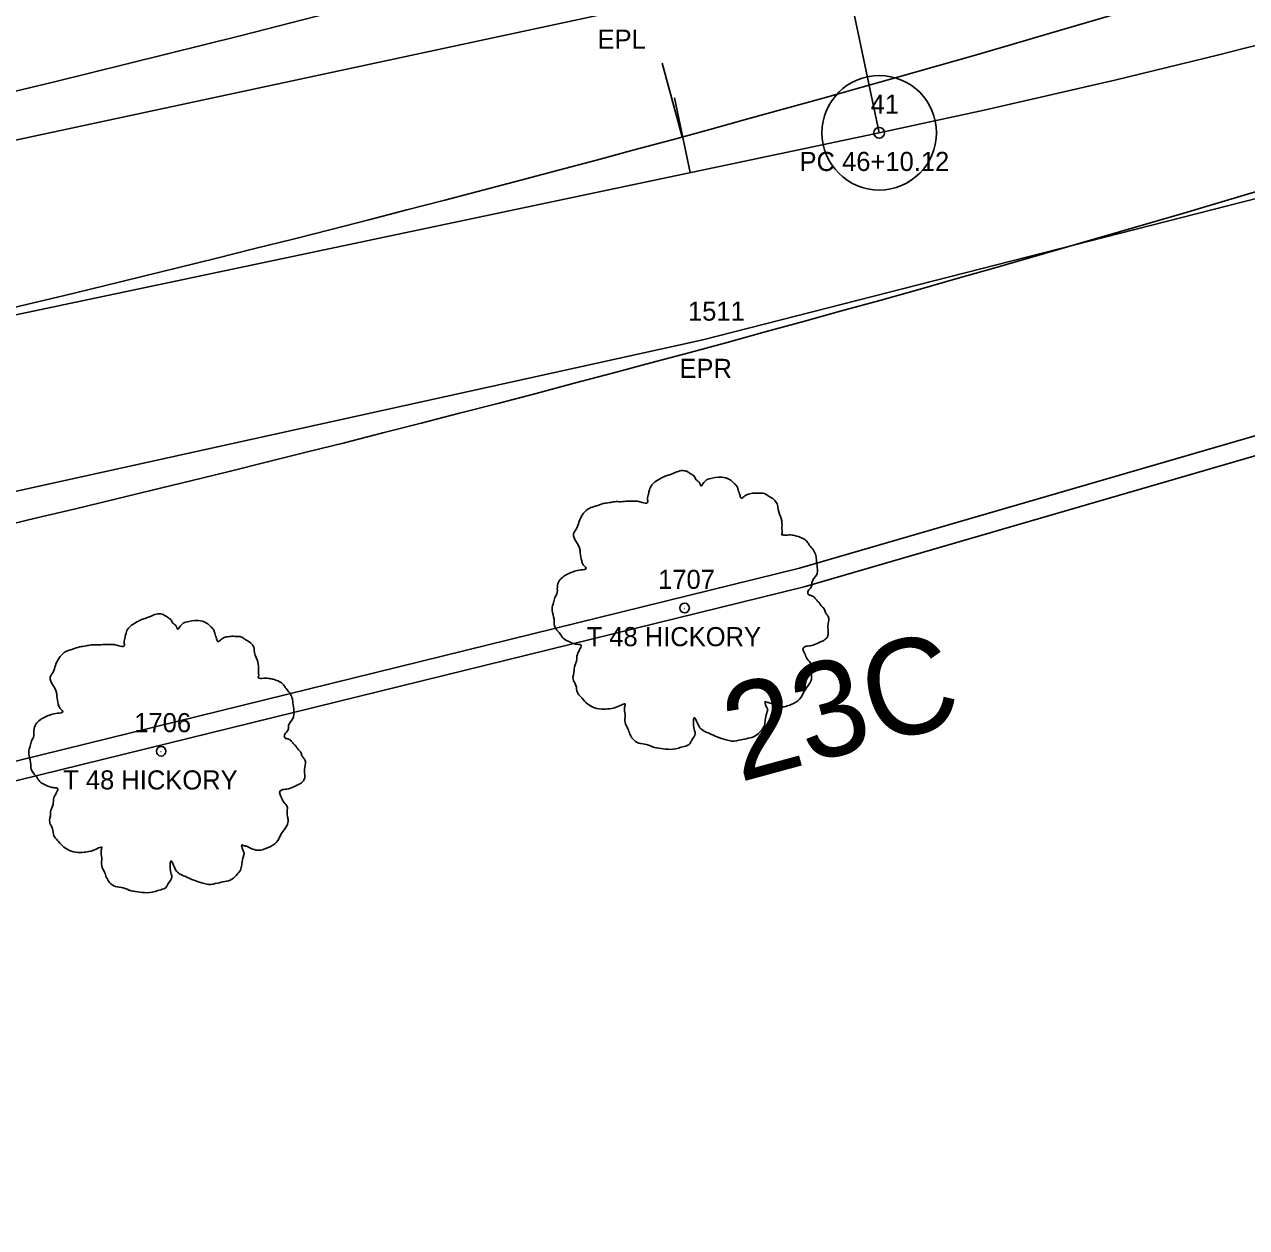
# Model space of a CAD drawing. Extents: x 1964982 to 1970452, y 1116335 to 1119906.
# Drawn here: x 1966640.1 to 1966704.1, y 1117364.6 to 1117427.6 of the extents above; entities that cross this region are included whole.
import ezdxf

# ---------------------------------------------------------------- set-up
doc = ezdxf.new("R2010")
doc.units = 0
for name, color, linetype in [('RD_EX_DV_Prop', 7, 'Continuous'), ('RD_EX_Road', 7, 'Continuous'), ('RD_EX_Road_txCode', 7, 'Continuous'), ('RD_EX_RW', 7, 'Continuous'), ('RD_EX_VEG', 7, 'Continuous'), ('RD_EX_VEG_txCode', 7, 'Continuous'), ('RD_HC_CL', 7, 'Continuous'), ('RD_HC_CL_Rel', 7, 'Continuous'), ('RD_HC_Data', 7, 'Continuous'), ('RD_HC_Data_Tic', 7, 'Continuous'), ('RD_HC_Data_Tic_Rel', 7, 'Continuous'), ('RD_HC_txCode', 7, 'Continuous'), ('RD_PD_CstnLmt', 7, 'Continuous'), ('RD_PD_Final_TrvlWay', 7, 'Continuous'), ('RD_PD_RW', 7, 'Continuous'), ('RD_PD_TX_CstnLmt', 7, 'Continuous'), ('RD_SMD_Locator', 7, 'Continuous')]:
    doc.layers.add(name, color=color, linetype=linetype)

msp = doc.modelspace()

# ---------------------------------------------------------------- linework, layer by layer
at = {"layer": 'RD_EX_DV_Prop'}
msp.add_line((1966425.261, 1117367.215), (1966684.872, 1117421.945), dxfattribs=at)
msp.add_arc((1966579.594, 1117921.318), 510.35, 281.90473, 291.99584, dxfattribs=at)
at = {"layer": 'RD_EX_Road'}
for points in [[(1966297.245, 1117343.102), (1966344.085, 1117357.038), (1966390.785, 1117368.561), (1966438.122, 1117379.082), (1966484.547, 1117389.131), (1966531.199, 1117398.733), (1966578.388, 1117408.593), (1966604.527, 1117414.058), (1966624.537, 1117418.323), (1966671.319, 1117428.348), (1966716.506, 1117439.32), (1966736.604, 1117445.59), (1966754.133, 1117451.442), (1966759.658, 1117453.517), (1966769.512, 1117457.475)], [(1965729.992, 1117080.297), (1965819.77, 1117119.134), (1965907.737, 1117159.312), (1965995.365, 1117199.039), (1966039.268, 1117218.497), (1966081.241, 1117237.148), (1966124.665, 1117256.555), (1966167.659, 1117275.555), (1966211.467, 1117293.627), (1966257.791, 1117311.581), (1966302.7, 1117327.207), (1966347.903, 1117339.982), (1966394.806, 1117351.637), (1966441.557, 1117361.865), (1966488.625, 1117372.057), (1966534.906, 1117381.34), (1966581.234, 1117390.947), (1966629.533, 1117400.947), (1966675.632, 1117411.107), (1966721.676, 1117422.847), (1966766.802, 1117438.972), (1966775.751, 1117440.571)]]:
    msp.add_lwpolyline(points, dxfattribs=at)
at = {"layer": 'RD_EX_RW'}
for points in [[(1966297.245, 1117343.102), (1966344.085, 1117357.038), (1966390.785, 1117368.561), (1966438.122, 1117379.082), (1966484.547, 1117389.131), (1966531.199, 1117398.733), (1966578.388, 1117408.593), (1966604.527, 1117414.058), (1966624.537, 1117418.323), (1966671.319, 1117428.348), (1966716.506, 1117439.32), (1966736.604, 1117445.59), (1966754.133, 1117451.442), (1966759.658, 1117453.517), (1966769.512, 1117457.475)], [(1965729.992, 1117080.297), (1965819.77, 1117119.134), (1965907.737, 1117159.312), (1965995.365, 1117199.039), (1966039.268, 1117218.497), (1966081.241, 1117237.148), (1966124.665, 1117256.555), (1966167.659, 1117275.555), (1966211.467, 1117293.627), (1966257.791, 1117311.581), (1966302.7, 1117327.207), (1966347.903, 1117339.982), (1966394.806, 1117351.637), (1966441.557, 1117361.865), (1966488.625, 1117372.057), (1966534.906, 1117381.34), (1966581.234, 1117390.947), (1966629.533, 1117400.947), (1966675.632, 1117411.107), (1966721.676, 1117422.847), (1966766.802, 1117438.972), (1966775.751, 1117440.571)]]:
    msp.add_lwpolyline(points, dxfattribs=at)
at = {"layer": 'RD_EX_VEG'}
for centre, radius in [((1966674.675, 1117397.058), 0.25), ((1966674.662, 1117397.04), 0.0001), ((1966647.251, 1117389.554), 0.25), ((1966647.238, 1117389.535), 0.0001)]:
    msp.add_circle(centre, radius, dxfattribs=at)
for points in [[(1966674.806, 1117404.226), (1966674.507, 1117404.251), (1966674.182, 1117404.151), (1966673.932, 1117404.051), (1966673.707, 1117403.976), (1966673.482, 1117403.876), (1966673.182, 1117403.701), (1966672.957, 1117403.501), (1966672.832, 1117403.251), (1966672.782, 1117403.026), (1966672.732, 1117402.751), (1966672.732, 1117402.576), (1966672.607, 1117402.551), (1966672.457, 1117402.576), (1966672.208, 1117402.651), (1966671.958, 1117402.651), (1966671.708, 1117402.651), (1966671.358, 1117402.626), (1966671.008, 1117402.626), (1966670.733, 1117402.576), (1966670.408, 1117402.526), (1966670.034, 1117402.401), (1966669.684, 1117402.276), (1966669.384, 1117402.027), (1966669.134, 1117401.552), (1966669.009, 1117401.202), (1966668.859, 1117400.952), (1966669.009, 1117400.502), (1966669.184, 1117400.152), (1966669.209, 1117399.952), (1966669.284, 1117399.528), (1966669.384, 1117399.303), (1966669.509, 1117399.103), (1966669.434, 1117399.078), (1966669.059, 1117399.028), (1966668.759, 1117398.928), (1966668.334, 1117398.703), (1966668.109, 1117398.478), (1966668.009, 1117398.153), (1966667.984, 1117397.803), (1966667.885, 1117397.604), (1966667.81, 1117397.329), (1966667.785, 1117397.254), (1966667.735, 1117396.929), (1966667.835, 1117396.479), (1966667.86, 1117396.129), (1966667.984, 1117395.904), (1966668.134, 1117395.729), (1966668.309, 1117395.479), (1966668.709, 1117395.255), (1966669.034, 1117395.155), (1966669.234, 1117395.13), (1966669.059, 1117394.63), (1966669.009, 1117394.28), (1966668.884, 1117393.88), (1966668.884, 1117393.805), (1966668.834, 1117393.33), (1966668.984, 1117393.005), (1966669.059, 1117392.631), (1966669.234, 1117392.406), (1966669.509, 1117392.106), (1966669.834, 1117391.881), (1966670.333, 1117391.756), (1966670.733, 1117391.781), (1966671.308, 1117391.956), (1966671.558, 1117392.031), (1966671.533, 1117391.856), (1966671.558, 1117391.481), (1966671.558, 1117391.056), (1966671.708, 1117390.732), (1966671.808, 1117390.457), (1966671.958, 1117390.207), (1966672.283, 1117389.982), (1966672.682, 1117389.907), (1966673.107, 1117389.757), (1966673.557, 1117389.682), (1966674.057, 1117389.657), (1966674.657, 1117389.807), (1966674.931, 1117389.932), (1966675.031, 1117390.107), (1966675.231, 1117390.482), (1966675.181, 1117390.707), (1966675.206, 1117391.306), (1966675.306, 1117391.131), (1966675.481, 1117390.781), (1966675.981, 1117390.482), (1966676.381, 1117390.307), (1966676.856, 1117390.157), (1966677.155, 1117390.082), (1966677.63, 1117390.157), (1966678.005, 1117390.232), (1966678.38, 1117390.357), (1966678.68, 1117390.632), (1966678.855, 1117390.906), (1966678.905, 1117391.181), (1966678.98, 1117391.556), (1966679.03, 1117391.731)], [(1966679.03, 1117391.731), (1966678.955, 1117391.906), (1966678.905, 1117392.156), (1966678.98, 1117392.131), (1966679.155, 1117392.081), (1966679.429, 1117391.956), (1966679.654, 1117391.881), (1966679.979, 1117391.906), (1966680.254, 1117392.006), (1966680.704, 1117392.281), (1966680.979, 1117392.756), (1966681.254, 1117393.155), (1966681.329, 1117393.48), (1966681.279, 1117393.705), (1966681.254, 1117394.205), (1966681.054, 1117394.455), (1966681.004, 1117394.58), (1966680.904, 1117394.98), (1966680.979, 1117395.03), (1966681.254, 1117395.08), (1966681.628, 1117395.205), (1966681.903, 1117395.329), (1966682.128, 1117395.504), (1966682.203, 1117395.729), (1966682.178, 1117396.129), (1966682.228, 1117396.529), (1966682.153, 1117396.679), (1966682.053, 1117396.829), (1966681.978, 1117397.029), (1966681.828, 1117397.179), (1966681.728, 1117397.329), (1966681.628, 1117397.429), (1966681.504, 1117397.579), (1966681.329, 1117397.703), (1966681.179, 1117397.753), (1966681.129, 1117397.903), (1966681.279, 1117398.103), (1966681.329, 1117398.203), (1966681.354, 1117398.428), (1966681.579, 1117398.778), (1966681.628, 1117399.178), (1966681.579, 1117399.603), (1966681.529, 1117399.878), (1966681.379, 1117400.152), (1966681.179, 1117400.402), (1966681.054, 1117400.577), (1966680.879, 1117400.702), (1966680.554, 1117400.827), (1966680.304, 1117400.877), (1966679.954, 1117400.877), (1966679.754, 1117400.927), (1966679.779, 1117400.977), (1966679.779, 1117401.127), (1966679.779, 1117401.402), (1966679.704, 1117401.852), (1966679.554, 1117402.351), (1966679.554, 1117402.376), (1966679.454, 1117402.626), (1966679.23, 1117402.826), (1966679.055, 1117402.926), (1966678.855, 1117403.051), (1966678.605, 1117403.076), (1966678.305, 1117403.076), (1966678.03, 1117403.026), (1966677.83, 1117402.926), (1966677.655, 1117402.801), (1966677.58, 1117402.951), (1966677.48, 1117403.251), (1966677.43, 1117403.401), (1966677.28, 1117403.576), (1966677.056, 1117403.776), (1966676.606, 1117403.901), (1966675.981, 1117403.826), (1966675.681, 1117403.626), (1966675.531, 1117403.451), (1966675.481, 1117403.576), (1966675.281, 1117403.776), (1966675.181, 1117403.951), (1966675.006, 1117404.076), (1966674.856, 1117404.176), (1966674.756, 1117404.226)], [(1966647.383, 1117396.721), (1966647.083, 1117396.746), (1966646.758, 1117396.646), (1966646.508, 1117396.546), (1966646.283, 1117396.471), (1966646.058, 1117396.371), (1966645.758, 1117396.196), (1966645.533, 1117395.996), (1966645.408, 1117395.746), (1966645.358, 1117395.522), (1966645.309, 1117395.247), (1966645.309, 1117395.072), (1966645.184, 1117395.047), (1966645.034, 1117395.072), (1966644.784, 1117395.147), (1966644.534, 1117395.147), (1966644.284, 1117395.147), (1966643.934, 1117395.122), (1966643.584, 1117395.122), (1966643.309, 1117395.072), (1966642.985, 1117395.022), (1966642.61, 1117394.897), (1966642.26, 1117394.772), (1966641.96, 1117394.522), (1966641.71, 1117394.047), (1966641.585, 1117393.697), (1966641.435, 1117393.447), (1966641.585, 1117392.998), (1966641.76, 1117392.648), (1966641.785, 1117392.448), (1966641.86, 1117392.023), (1966641.96, 1117391.798), (1966642.085, 1117391.598), (1966642.01, 1117391.573), (1966641.635, 1117391.523), (1966641.335, 1117391.423), (1966640.91, 1117391.198), (1966640.686, 1117390.974), (1966640.586, 1117390.649), (1966640.561, 1117390.299), (1966640.461, 1117390.099), (1966640.386, 1117389.824), (1966640.361, 1117389.749), (1966640.311, 1117389.424), (1966640.411, 1117388.974), (1966640.436, 1117388.625), (1966640.561, 1117388.4), (1966640.711, 1117388.225), (1966640.885, 1117387.975), (1966641.285, 1117387.75), (1966641.61, 1117387.65), (1966641.81, 1117387.625), (1966641.635, 1117387.125), (1966641.585, 1117386.775), (1966641.46, 1117386.376), (1966641.46, 1117386.301), (1966641.41, 1117385.826), (1966641.56, 1117385.501), (1966641.635, 1117385.126), (1966641.81, 1117384.901), (1966642.085, 1117384.601), (1966642.41, 1117384.376), (1966642.91, 1117384.251), (1966643.309, 1117384.276), (1966643.884, 1117384.451), (1966644.134, 1117384.526), (1966644.109, 1117384.351), (1966644.134, 1117383.977), (1966644.134, 1117383.552), (1966644.284, 1117383.227), (1966644.384, 1117382.952), (1966644.534, 1117382.702), (1966644.859, 1117382.477), (1966645.259, 1117382.402), (1966645.683, 1117382.252), (1966646.133, 1117382.177), (1966646.633, 1117382.152), (1966647.233, 1117382.302), (1966647.508, 1117382.427), (1966647.608, 1117382.602), (1966647.807, 1117382.977), (1966647.757, 1117383.202), (1966647.782, 1117383.802), (1966647.882, 1117383.627), (1966648.057, 1117383.277), (1966648.557, 1117382.977), (1966648.957, 1117382.802), (1966649.432, 1117382.652), (1966649.732, 1117382.577), (1966650.206, 1117382.652), (1966650.581, 1117382.727), (1966650.956, 1117382.852), (1966651.256, 1117383.127), (1966651.431, 1117383.402), (1966651.481, 1117383.677), (1966651.556, 1117384.052), (1966651.606, 1117384.226)], [(1966651.606, 1117384.226), (1966651.531, 1117384.401), (1966651.481, 1117384.651), (1966651.556, 1117384.626), (1966651.731, 1117384.576), (1966652.006, 1117384.451), (1966652.231, 1117384.376), (1966652.555, 1117384.401), (1966652.83, 1117384.501), (1966653.28, 1117384.776), (1966653.555, 1117385.251), (1966653.83, 1117385.651), (1966653.905, 1117385.976), (1966653.855, 1117386.201), (1966653.83, 1117386.7), (1966653.63, 1117386.95), (1966653.58, 1117387.075), (1966653.48, 1117387.475), (1966653.555, 1117387.525), (1966653.83, 1117387.575), (1966654.205, 1117387.7), (1966654.48, 1117387.825), (1966654.704, 1117388), (1966654.779, 1117388.225), (1966654.754, 1117388.625), (1966654.804, 1117389.024), (1966654.729, 1117389.174), (1966654.629, 1117389.324), (1966654.554, 1117389.524), (1966654.405, 1117389.674), (1966654.305, 1117389.824), (1966654.205, 1117389.924), (1966654.08, 1117390.074), (1966653.905, 1117390.199), (1966653.755, 1117390.249), (1966653.705, 1117390.399), (1966653.855, 1117390.599), (1966653.905, 1117390.699), (1966653.93, 1117390.924), (1966654.155, 1117391.273), (1966654.205, 1117391.673), (1966654.155, 1117392.098), (1966654.105, 1117392.373), (1966653.955, 1117392.648), (1966653.755, 1117392.898), (1966653.63, 1117393.073), (1966653.455, 1117393.198), (1966653.13, 1117393.323), (1966652.88, 1117393.372), (1966652.53, 1117393.372), (1966652.33, 1117393.422), (1966652.355, 1117393.472), (1966652.355, 1117393.622), (1966652.355, 1117393.897), (1966652.28, 1117394.347), (1966652.131, 1117394.847), (1966652.131, 1117394.872), (1966652.031, 1117395.122), (1966651.806, 1117395.322), (1966651.631, 1117395.422), (1966651.431, 1117395.547), (1966651.181, 1117395.572), (1966650.881, 1117395.572), (1966650.606, 1117395.522), (1966650.406, 1117395.422), (1966650.231, 1117395.297), (1966650.156, 1117395.447), (1966650.056, 1117395.746), (1966650.006, 1117395.896), (1966649.857, 1117396.071), (1966649.632, 1117396.271), (1966649.182, 1117396.396), (1966648.557, 1117396.321), (1966648.257, 1117396.121), (1966648.107, 1117395.946), (1966648.057, 1117396.071), (1966647.857, 1117396.271), (1966647.757, 1117396.446), (1966647.583, 1117396.571), (1966647.433, 1117396.671), (1966647.333, 1117396.721)]]:
    msp.add_spline(points, degree=3, dxfattribs=at)
at = {"layer": 'RD_HC_CL'}
msp.add_line((1966425.261, 1117367.215), (1966684.871, 1117421.945), dxfattribs=at)
msp.add_arc((1966579.594, 1117921.318), 510.35, 281.90472, 291.99584, dxfattribs=at)
at = {"layer": 'RD_HC_CL_Rel'}
msp.add_arc((1966373.74, 1118527.456), 1145.915, 281.904723, 295.046328, dxfattribs=at)
at = {"layer": 'RD_HC_Data'}
msp.add_line((1966684.871, 1117421.945), (1966664.447, 1117518.825), dxfattribs=at)
for radius in [3, 0.282]:
    msp.add_circle((1966684.871, 1117421.945), radius, dxfattribs=at)
at = {"layer": 'RD_HC_Data_Tic'}
msp.add_line((1966674.973, 1117419.859), (1966674.148, 1117423.773), dxfattribs=at)
at = {"layer": 'RD_HC_Data_Tic_Rel'}
msp.add_line((1966674.542, 1117421.726), (1966673.492, 1117425.586), dxfattribs=at)
at = {"layer": 'RD_PD_CstnLmt'}
for p, q in [((1966729.686, 1117413.368), (1966680.687, 1117399.137)), ((1966680.687, 1117399.137), (1966631.148, 1117386.955))]:
    msp.add_line(p, q, dxfattribs=at)
at = {"layer": 'RD_PD_Final_TrvlWay'}
for radius in [1134.915, 1156.915]:
    msp.add_arc((1966373.74, 1118527.456), radius, 281.904723, 295.046328, dxfattribs=at)
at = {"layer": 'RD_PD_RW'}
for p, q in [((1966729.954, 1117412.405), (1966680.946, 1117398.171)), ((1966680.946, 1117398.171), (1966631.369, 1117385.979))]:
    msp.add_line(p, q, dxfattribs=at)
at = {"layer": 'RD_SMD_Locator'}
for centre in [(1966684.871, 1117421.945), (1966684.871, 1117421.945), (1966675.632, 1117411.107), (1966675.632, 1117411.107)]:
    msp.add_circle(centre, 0.001, dxfattribs=at)

# ---------------------------------------------------------------- texts
at = {"layer": 'RD_EX_Road_txCode'}
for s, p in [('EPL', (1966670.114, 1117426.348)), ('EPL', (1966670.114, 1117426.348)), ('1511', (1966674.853, 1117412.107)), ('1511', (1966674.853, 1117412.107)), ('EPR', (1966674.404, 1117409.107)), ('EPR', (1966674.404, 1117409.107))]:
    msp.add_text(s, height=1, dxfattribs=at).set_placement(p)
at = {"layer": 'RD_EX_VEG_txCode'}
for s, p in [('1707', (1966673.289, 1117398.058)), ('T 48 HICKORY', (1966669.541, 1117395.058)), ('1706', (1966645.841, 1117390.554)), ('T 48 HICKORY', (1966642.117, 1117387.554))]:
    msp.add_text(s, height=1, dxfattribs=at).set_placement(p)
at = {"layer": 'RD_HC_txCode'}
for s, p in [('41', (1966684.423, 1117422.945)), ('41', (1966684.423, 1117422.945)), ('PC 46+10.12', (1966680.698, 1117419.945)), ('PC 46+10.12', (1966680.698, 1117419.945))]:
    msp.add_text(s, height=1, dxfattribs=at).set_placement(p)
at = {"layer": 'RD_PD_TX_CstnLmt'}
msp.add_text('23C', height=5, rotation=15.21843, dxfattribs=at).set_placement((1966677.552, 1117387.921))

doc.saveas('drawing.dxf')
